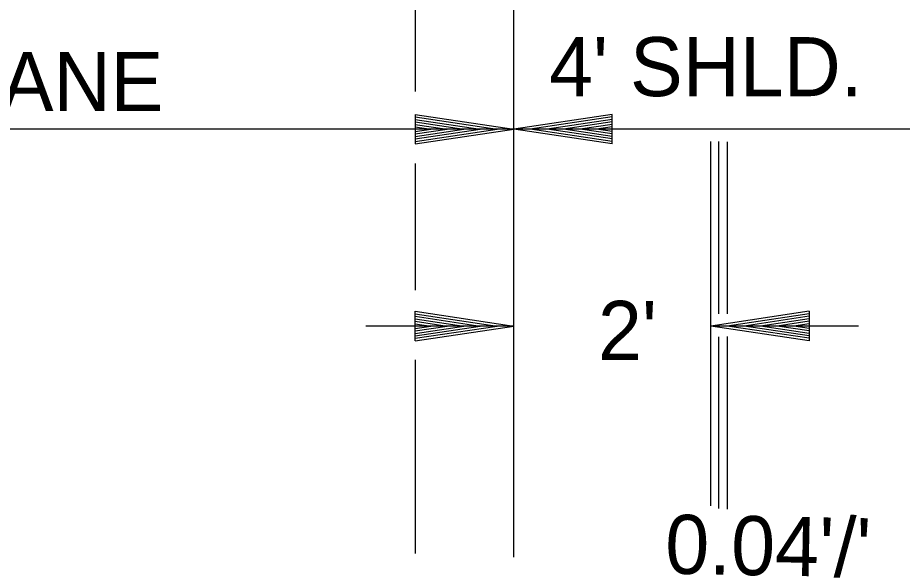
# Model space of a CAD drawing. Extents: x 2478 to 3210, y 439 to 841.
# Drawn here: x 3040.31 to 3058.28, y 597.34 to 608.39 of the extents above; entities that cross this region are included whole.
import ezdxf

# ---------------------------------------------------------------- set-up
doc = ezdxf.new("R2010")
doc.units = 0
doc.layers.add('R_Annotation', color=7, linetype='Continuous')
doc.layers.add('R_Dimension', color=7, linetype='Continuous')

msp = doc.modelspace()

# ---------------------------------------------------------------- linework, layer by layer
at = {"layer": 'R_Dimension'}
for p, q in [((3050.387, 597.431), (3050.387, 611.125)), ((3048.387, 610.625), (3048.387, 606.892)), ((3048.387, 606.425), (3050.387, 606.125)), ((3048.387, 606.425), (3048.387, 605.825)), ((3048.387, 606.375), (3050.053, 606.125)), ((3048.387, 606.324), (3049.709, 606.125)), ((3048.387, 606.274), (3049.376, 606.125)), ((3052.387, 606.425), (3050.387, 606.125)), ((3052.387, 606.375), (3050.721, 606.125)), ((3052.387, 606.324), (3051.065, 606.125)), ((3052.387, 606.274), (3051.398, 606.125)), ((3052.387, 605.825), (3052.387, 606.425)), ((3067.845, 606.125), (2988.928, 606.125)), ((3048.387, 606.222), (3049.037, 606.125)), ((3048.387, 606.172), (3048.703, 606.125)), ((3048.387, 605.825), (3050.387, 606.125)), ((3048.387, 606.027), (3049.037, 606.125)), ((3048.387, 605.926), (3049.709, 606.125)), ((3048.387, 605.875), (3050.053, 606.125)), ((3048.387, 605.976), (3049.376, 606.125)), ((3048.387, 606.078), (3048.703, 606.125)), ((3052.387, 605.825), (3050.387, 606.125)), ((3052.387, 605.875), (3050.721, 606.125)), ((3052.387, 605.926), (3051.065, 606.125)), ((3052.387, 605.976), (3051.398, 606.125)), ((3052.387, 606.223), (3051.737, 606.125)), ((3052.387, 606.028), (3051.737, 606.125)), ((3052.387, 606.172), (3052.071, 606.125)), ((3052.387, 606.078), (3052.071, 606.125)), ((3054.39, 598.473), (3054.39, 605.871)), ((3054.557, 602.372), (3054.557, 605.871)), ((3054.728, 602.372), (3054.728, 605.868)), ((3048.387, 605.428), (3048.387, 602.853)), ((3048.387, 602.425), (3050.387, 602.125)), ((3048.387, 601.825), (3048.387, 602.425)), ((3048.387, 602.375), (3050.053, 602.125)), ((3048.387, 602.324), (3049.709, 602.125)), ((3056.39, 602.425), (3054.39, 602.125)), ((3056.39, 602.375), (3054.724, 602.125)), ((3056.39, 602.324), (3055.068, 602.125)), ((3056.39, 602.425), (3056.39, 601.825)), ((3050.387, 602.125), (3047.387, 602.125)), ((3048.387, 602.274), (3049.376, 602.125)), ((3048.387, 602.223), (3049.037, 602.125)), ((3048.387, 602.172), (3048.703, 602.125)), ((3048.387, 601.825), (3050.387, 602.125)), ((3048.387, 602.028), (3049.037, 602.125)), ((3048.387, 601.926), (3049.709, 602.125)), ((3048.387, 601.875), (3050.053, 602.125)), ((3048.387, 601.976), (3049.376, 602.125)), ((3048.387, 602.078), (3048.703, 602.125)), ((3056.39, 601.825), (3054.39, 602.125)), ((3057.39, 602.125), (3054.39, 602.125)), ((3056.39, 601.875), (3054.724, 602.125)), ((3056.39, 601.926), (3055.068, 602.125)), ((3056.39, 602.274), (3055.401, 602.125)), ((3056.39, 601.976), (3055.401, 602.125)), ((3056.39, 602.222), (3055.74, 602.125)), ((3056.39, 602.027), (3055.74, 602.125)), ((3056.39, 602.172), (3056.074, 602.125)), ((3056.39, 602.078), (3056.074, 602.125)), ((3054.557, 598.417), (3054.557, 601.905)), ((3054.728, 598.401), (3054.728, 601.91)), ((3048.387, 601.435), (3048.387, 597.501))]:
    msp.add_line(p, q, dxfattribs=at)

# ---------------------------------------------------------------- texts
at = {"layer": 'R_Annotation'}
for s, p in [("4' SHLD.", (3051.105, 606.795)), ("11' LANE", (3036.541, 606.492)), ("2'", (3052.099, 601.436))]:
    msp.add_text(s, height=1.2, dxfattribs=at).set_placement(p)
msp.add_text("0.04'/'", height=1.2, rotation=358.9387, dxfattribs=at).set_placement((3053.456, 597.096))

doc.saveas('drawing.dxf')
